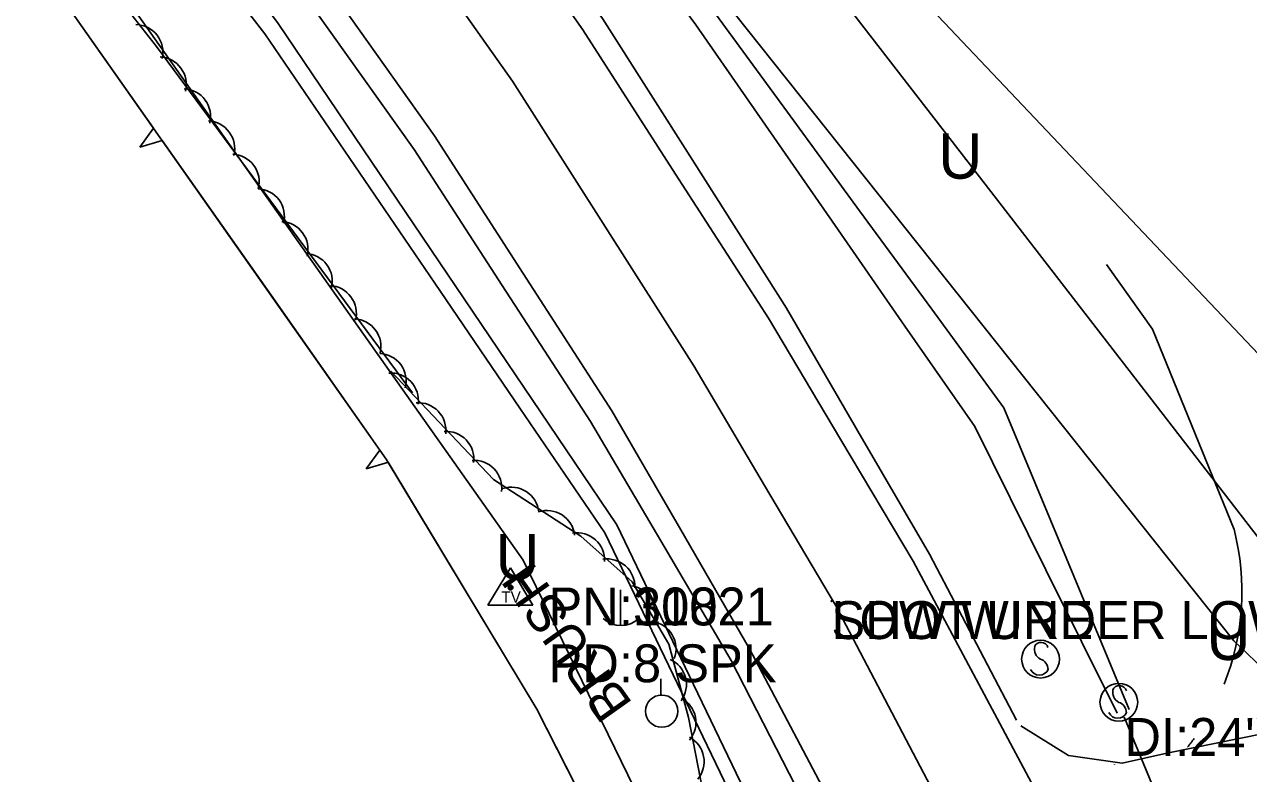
# Model space of a CAD drawing. Extents: x 954793 to 988390, y 1867850 to 1924428.
# Drawn here: x 964619 to 964780.5, y 1900331.1 to 1900429.9 of the extents above; entities that cross this region are included whole.
import ezdxf

# ---------------------------------------------------------------- set-up
doc = ezdxf.new("R2010")
doc.units = 0
for name, color, linetype in [('Default', 7, 'Continuous'), ('S_DITCHLINE', 7, 'Continuous'), ('S_DRG_PT_SYM', 7, 'Continuous'), ('S_DRIVEWAY', 7, 'Continuous'), ('S_EDGE_PAVEMENT', 7, 'Continuous'), ('S_ELECTRIC_UTILITIES_ANNOT', 7, 'Continuous'), ('S_FIBER_OPTIC_CABLE', 7, 'Continuous'), ('S_GRAVEL_ROAD', 7, 'Continuous'), ('S_GRD_PT_SYM', 7, 'Continuous'), ('S_MISC_TOPO_POINT', 7, 'Continuous'), ('S_PAVEMENT_CROWN', 7, 'Continuous'), ('S_SECONDARY_CTL', 7, 'Continuous'), ('S_SECONDARY_CTL_ANNOT', 7, 'Continuous'), ('S_SHOULDER', 7, 'Continuous'), ('S_SIDE_DRAIN', 7, 'Continuous'), ('S_SIDE_DRAIN_ANNOT', 7, 'Continuous'), ('S_SIGN', 7, 'Continuous'), ('S_TREE', 7, 'Continuous'), ('S_TREE_ANNOT', 7, 'Continuous'), ('S_UNDERGROUND_CABLE', 7, 'Continuous'), ('S_UTILITY_POLE', 7, 'Continuous'), ('S_UTL_PT_SYM', 7, 'Continuous'), ('S_WATER_UTILITIES', 7, 'Continuous')]:
    doc.layers.add(name, color=color, linetype=linetype)

msp = doc.modelspace()

# ---------------------------------------------------------------- linework, layer by layer
at = {"layer": 'S_DITCHLINE'}
for points in [[(964764.73, 1900339.6), (964756.46, 1900359.49), (964748.19, 1900379.38), (964738.68, 1900392.37), (964729.17, 1900405.36), (964719.66, 1900418.35), (964710.14, 1900431.35), (964699.21, 1900446.53), (964688.28, 1900461.71), (964677.34, 1900476.89), (964666.41, 1900492.07), (964660.34, 1900500.66)], [(964763.14, 1900339.09), (964753.74, 1900358), (964744.35, 1900376.91), (964735.15, 1900390.15), (964725.96, 1900403.4), (964716.77, 1900416.64), (964707.57, 1900429.89), (964696.59, 1900444.73), (964685.61, 1900459.58), (964674.62, 1900474.43), (964663.64, 1900489.27), (964657.32, 1900498.36)], [(964714.02, 1900328.82), (964705.58, 1900346.37), (964697.13, 1900363.92), (964685.97, 1900380.45), (964674.81, 1900396.98), (964663.64, 1900413.51), (964652.48, 1900430.04), (964644.78, 1900440.5), (964637.07, 1900450.97), (964629.37, 1900461.43), (964621.66, 1900471.9)], [(964712.45, 1900327.78), (964703.99, 1900345.33), (964695.54, 1900362.89), (964684.33, 1900379.34), (964673.11, 1900395.8), (964661.9, 1900412.26), (964650.69, 1900428.71), (964642.77, 1900438.93), (964634.84, 1900449.15), (964626.92, 1900459.37), (964619, 1900469.58)]]:
    msp.add_lwpolyline(points, dxfattribs=at)
at = {"layer": 'S_DRG_PT_SYM'}
msp.add_lwpolyline([(964764.09, 1900338.46), (964764.09, 1900338.51), (964764.09, 1900338.46), (964764.04, 1900338.46), (964764.09, 1900338.46), (964764.09, 1900338.41), (964764.09, 1900338.46), (964764.14, 1900338.46)], dxfattribs=at)
at = {"layer": 'S_DRIVEWAY'}
msp.add_lwpolyline([(964778.56, 1900363.34), (964767.82, 1900389.73), (964761.73, 1900398.29)], dxfattribs=at)
for start_param, end_param in [(4.608783, 5.240125), (4.315663, 4.359246)]:
    msp.add_ellipse((964746.77, 1900355.09), major_axis=(8.95, 31.69), ratio=0.996478, start_param=start_param, end_param=end_param, dxfattribs=at)
at = {"layer": 'S_EDGE_PAVEMENT'}
for points in [[(964856.03, 1900102.29), (964851.17, 1900113.05), (964842.05, 1900133.24), (964834.59, 1900149.79), (964827.13, 1900166.33), (964819.02, 1900184.19), (964810.92, 1900202.05), (964804.67, 1900215.97), (964798.43, 1900229.9), (964789.69, 1900249.21), (964780.95, 1900268.53), (964770.89, 1900290.7), (964762.58, 1900308.03), (964754.27, 1900325.37), (964745.24, 1900342.26), (964736.21, 1900359.15), (964726.67, 1900375.16), (964717.14, 1900391.17), (964704.89, 1900410.18), (964692.64, 1900429.2), (964681.94, 1900444.58), (964671.24, 1900459.96), (964659, 1900475.53), (964646.77, 1900491.1)], [(964820.97, 1900120.67), (964819.99, 1900122.84), (964812.33, 1900139.89), (964804.68, 1900156.93), (964796.54, 1900174.83), (964788.4, 1900192.72), (964782.35, 1900206.05), (964776.3, 1900219.38), (964767.36, 1900239.02), (964758.42, 1900258.67), (964748.49, 1900280.3), (964740.3, 1900297.37), (964732.1, 1900314.44), (964723.38, 1900331.01), (964714.65, 1900347.58), (964705.56, 1900363.27), (964696.47, 1900378.95), (964684.77, 1900397.09), (964673.08, 1900415.23), (964662.11, 1900430.73), (964651.13, 1900446.23), (964639.36, 1900461.44), (964627.58, 1900476.65)], [(964782.47, 1900336.41), (964769.69, 1900333.83), (964763.82, 1900332.5), (964756.74, 1900333.52), (964750.42, 1900337.41)]]:
    msp.add_lwpolyline(points, dxfattribs=at)
at = {"layer": 'S_FIBER_OPTIC_CABLE'}
msp.add_line((964743.18, 1900412.14), (964698.41, 1900470.05), dxfattribs=at)
at = {"layer": 'S_GRAVEL_ROAD'}
msp.add_lwpolyline([(964762.81, 1900332.35), (964762.77, 1900332.34)], dxfattribs=at)
at = {"layer": 'S_GRD_PT_SYM'}
msp.add_lwpolyline([(964725.44, 1900353.87), (964725.44, 1900353.92), (964725.44, 1900353.87), (964725.39, 1900353.87), (964725.44, 1900353.87), (964725.44, 1900353.82), (964725.44, 1900353.87), (964725.49, 1900353.87)], dxfattribs=at)
at = {"layer": 'S_PAVEMENT_CROWN'}
msp.add_lwpolyline([(964743.68, 1900319.67), (964734.84, 1900336.51), (964726, 1900353.35), (964716.64, 1900369.13), (964707.29, 1900384.92), (964695.32, 1900403.69), (964683.36, 1900422.46), (964672.5, 1900437.84), (964661.65, 1900453.22), (964649.52, 1900468.68), (964637.39, 1900484.14)], dxfattribs=at)
at = {"layer": 'S_SECONDARY_CTL'}
for p, q in [((964683.12, 1900358.28), (964680.11, 1900353.32)), ((964683.12, 1900358.28), (964686.07, 1900353.32)), ((964680.11, 1900353.32), (964686.07, 1900353.32))]:
    msp.add_line(p, q, dxfattribs=at)
for radius in [0.311, 0.183, 0.103]:
    msp.add_circle((964683.12, 1900355.67), radius, dxfattribs=at)
at = {"layer": 'S_SHOULDER'}
for points in [[(964749.86, 1900338.16), (964738.37, 1900360.06), (964728.95, 1900376.29), (964719.53, 1900392.52), (964707.38, 1900411.62), (964695.23, 1900430.72), (964684.39, 1900446.08), (964673.54, 1900461.45), (964661.32, 1900477.13), (964649.1, 1900492.8)], [(964744.58, 1900281), (964737.41, 1900295.91), (964729.18, 1900313), (964720.7, 1900329.53), (964712.22, 1900346.06), (964702.94, 1900361.82), (964693.66, 1900377.58), (964682.02, 1900395.5), (964670.39, 1900413.42), (964659.42, 1900428.86), (964648.44, 1900444.3), (964636.62, 1900459.37), (964624.8, 1900474.44)]]:
    msp.add_lwpolyline(points, dxfattribs=at)
at = {"layer": 'S_SIDE_DRAIN'}
msp.add_line((964764.09, 1900338.46), (964771.11, 1900321.73), dxfattribs=at)
at = {"layer": 'S_SIGN'}
for centre in [(964753.03, 1900346.22), (964763.36, 1900340.53)]:
    msp.add_circle(centre, 2.49, dxfattribs=at)
for centre, radius, start, end in [((964753.72, 1900347.55), 1.5, 167.1196, 241.9813), ((964753.1, 1900347.49), 0.95, 16.5258, 156.8957), ((964752.62, 1900344.88), 1.4, 358.6529, 73.7063), ((964752.88, 1900345.4), 1.28, 204.641, 335.359), ((964763.44, 1900341.79), 0.95, 16.5258, 156.8957), ((964764.05, 1900341.85), 1.5, 167.1196, 241.9813), ((964763.21, 1900339.7), 1.28, 204.641, 335.359), ((964762.95, 1900339.18), 1.4, 358.6529, 73.7063)]:
    msp.add_arc(centre, radius, start, end, dxfattribs=at)
at = {"layer": 'S_TREE'}
for p, q in [((964636.04, 1900416.24), (964634.21, 1900413.76)), ((964634.21, 1900413.76), (964637.17, 1900414.63)), ((964665.89, 1900373.8), (964664.07, 1900371.32)), ((964664.07, 1900371.32), (964667.02, 1900372.2))]:
    msp.add_line(p, q, dxfattribs=at)
for points in [[(964628.69, 1900436.92), (964636.43, 1900427), (964670.17, 1900381.34)], [(964623.65, 1900433.84), (964636.04, 1900416.24)], [(964623.65, 1900433.84), (964666.73, 1900372.61), (964686.58, 1900339.64), (964703.1, 1900307.14), (964719.42, 1900271.47)], [(964637.17, 1900414.63), (964651.53, 1900394.22)], [(964651.53, 1900394.22), (964665.89, 1900373.8)], [(964667.31, 1900384.2), (964680.89, 1900369.91), (964692.41, 1900362.46), (964699.16, 1900356.43), (964704.01, 1900348.19), (964706.59, 1900338.54), (964708.47, 1900328.83), (964709.78, 1900322.16), (964711.25, 1900315.08)], [(964666.99, 1900372.18), (964679.86, 1900350.8)], [(964679.86, 1900350.8), (964686.58, 1900339.64), (964691.99, 1900329)]]:
    msp.add_lwpolyline(points, dxfattribs=at)
for centre, start, end in [((964633.62, 1900426.27), 347.1292, 88.7261), ((964636.71, 1900422.01), 345.6644, 87.2614), ((964639.91, 1900417.8), 345.6644, 87.2614), ((964643.09, 1900413.56), 345.6644, 87.2614), ((964646.32, 1900409.18), 345.6644, 87.2614), ((964649.65, 1900404.62), 345.6644, 87.2614), ((964652.76, 1900400.29), 345.6644, 87.2614), ((964655.96, 1900396.08), 345.6644, 87.2614), ((964659.14, 1900391.84), 345.6644, 87.2614), ((964662.38, 1900387.46), 345.6644, 87.2614), ((964665.71, 1900382.9), 345.6644, 87.2614), ((964667.33, 1900380.32), 352.719, 94.3159), ((964670.95, 1900376.4), 352.719, 94.3159), ((964674.64, 1900372.62), 352.719, 94.3159), ((964678.32, 1900368.8), 352.719, 94.3159), ((964683.22, 1900365.27), 6.3286, 107.9255), ((964687.94, 1900362.18), 6.3286, 107.9255), ((964691.88, 1900359.26), 357.4573, 99.0542), ((964695.87, 1900355.8), 357.4573, 99.0542), ((964698.56, 1900352.28), 339.6257, 81.2226), ((964701.31, 1900347.59), 339.6257, 81.2226), ((964702.68, 1900342.87), 324.2281, 65.825), ((964703.94, 1900337.88), 320.1047, 61.7016), ((964705.01, 1900332.71), 320.1047, 61.7016)]:
    msp.add_arc(centre, 3.64, start, end, dxfattribs=at)
at = {"layer": 'S_UNDERGROUND_CABLE'}
for p, q in [((964743.18, 1900412.14), (964698.42, 1900470.02)), ((964684.77, 1900359.26), (964626.18, 1900442.25)), ((964778.55, 1900348.65), (964710.96, 1900433.59)), ((964786, 1900356.72), (964743.18, 1900412.14)), ((964732.94, 1900260.68), (964684.77, 1900359.26)), ((964826.04, 1900303), (964778.55, 1900348.65))]:
    msp.add_line(p, q, dxfattribs=at)
at = {"layer": 'S_UTILITY_POLE'}
for p, q in [((964697.63, 1900355.37), (964697.63, 1900350.64)), ((964702.94, 1900341.51), (964702.94, 1900343.61))]:
    msp.add_line(p, q, dxfattribs=at)
msp.add_circle((964703.06, 1900339.36), 2.13, dxfattribs=at)
msp.add_arc((964697.69, 1900354.07), 3.41, 226.3972, 313.6028, dxfattribs=at)
at = {"layer": 'S_UTL_PT_SYM'}
for points in [[(964743.18, 1900412.14), (964743.18, 1900412.19), (964743.18, 1900412.14), (964743.13, 1900412.14), (964743.18, 1900412.14), (964743.18, 1900412.09), (964743.18, 1900412.14), (964743.23, 1900412.14)], [(964725.44, 1900353.87), (964725.44, 1900353.92), (964725.44, 1900353.87), (964725.39, 1900353.87), (964725.44, 1900353.87), (964725.44, 1900353.82), (964725.44, 1900353.87), (964725.49, 1900353.87)]]:
    msp.add_lwpolyline(points, dxfattribs=at)
at = {"layer": 'S_WATER_UTILITIES'}
msp.add_line((964805.04, 1900361.86), (964717.02, 1900454.8), dxfattribs=at)

# ---------------------------------------------------------------- texts
at = {"layer": 'Default'}
for p in [(964739.55, 1900409.59), (964681.14, 1900356.71), (964774.92, 1900346.11)]:
    msp.add_text('U', height=6, rotation=360, dxfattribs=at).set_placement(p)
at = {"layer": 'S_ELECTRIC_UTILITIES_ANNOT'}
msp.add_text('LOW WIRE', height=5, dxfattribs=at).set_placement((964725.44, 1900348.87))
at = {"layer": 'S_MISC_TOPO_POINT'}
msp.add_text('SHOT UNDER LOW WIRE', height=5, dxfattribs=at).set_placement((964725.44, 1900348.87))
at = {"layer": 'S_SECONDARY_CTL'}
msp.add_text('TV', height=1.5, rotation=360, dxfattribs=at).set_placement((964681.91, 1900353.66))
at = {"layer": 'S_SECONDARY_CTL_ANNOT'}
for s, p in [('PN:1182', (964688.12, 1900350.67)), ('PN:30021', (964688.12, 1900350.67)), ('PD:8 SPK', (964688.12, 1900343.17)), ('PD:8 SPK', (964688.12, 1900343.17))]:
    msp.add_text(s, height=5, dxfattribs=at).set_placement(p)
at = {"layer": 'S_SIDE_DRAIN_ANNOT'}
msp.add_text('DI:24" TY:CMP CN:100 PERCENT FI', height=5, dxfattribs=at).set_placement((964764.09, 1900333.46))
at = {"layer": 'S_TREE_ANNOT'}
msp.add_text('BRUSH', height=5, rotation=125.3444, dxfattribs=at).set_placement((964699.32, 1900340.32))

doc.saveas('drawing.dxf')
